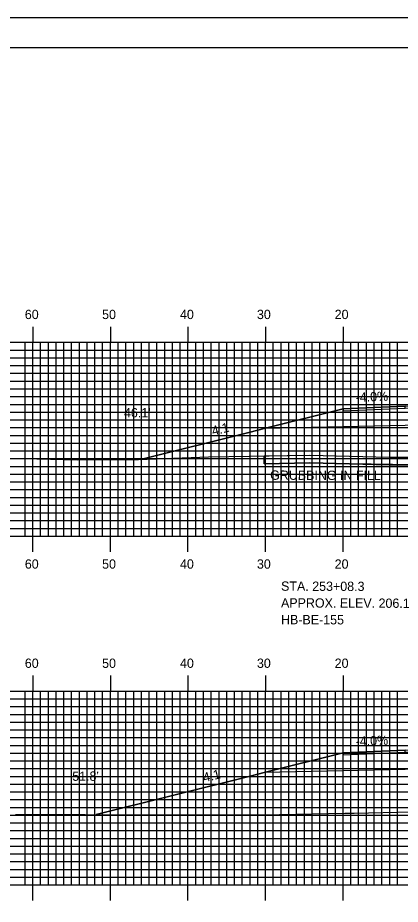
# Model space of a CAD drawing. Extents: x 1804290 to 1804634, y 442591 to 442811.
# Drawn here: x 1804394.2 to 1804443.5, y 442696.2 to 442810.5 of the extents above; entities that cross this region are included whole.
import ezdxf

# ---------------------------------------------------------------- set-up
doc = ezdxf.new("R2010")
doc.units = 0
for name, color, linetype in [('ANNOTATION', 7, 'Continuous'), ('BORDER', 7, 'Continuous'), ('BORING - REFUSAL', 7, 'Continuous'), ('D_Roadway_Centerline', 7, 'Continuous'), ('D_Roadway_Edge_Shoulder', 7, 'Continuous'), ('D_Roadway_SlopeLines', 7, 'Continuous'), ('D_Roadway_SubGrade', 7, 'Continuous'), ('D_Text_Standard', 7, 'Continuous'), ('GRUBBING IN FILL', 7, 'Continuous'), ('H_V ANNOTATION', 7, 'Continuous'), ('MAJOR', 7, 'Continuous'), ('MINOR', 7, 'Continuous'), ('PLOT BOUNDARY', 7, 'Continuous'), ('S_Roadway_Centerline', 7, 'Continuous')]:
    doc.layers.add(name, color=color, linetype=linetype)

msp = doc.modelspace()

# ---------------------------------------------------------------- linework, layer by layer
at = {"layer": 'BORDER'}
msp.add_lwpolyline([(1804306.57, 442596.67), (1804626.57, 442596.67), (1804626.57, 442806.67), (1804306.57, 442806.67)], close=True, dxfattribs=at)
at = {"layer": 'D_Roadway_Centerline'}
for points in [[(1804410.07, 442753.57), (1804424.17, 442757.1), (1804425.99, 442757.55), (1804436.17, 442760.1), (1804444.17, 442760.42), (1804456.17, 442760.71), (1804468.17, 442760.99), (1804476.17, 442760.67), (1804486.34, 442758.13), (1804501.85, 442754.25)], [(1804404.33, 442707.76), (1804424.17, 442712.72), (1804425.99, 442713.18), (1804436.17, 442715.72), (1804444.17, 442716.04), (1804456.17, 442716.33), (1804468.17, 442716.62), (1804476.17, 442716.3), (1804486.34, 442713.76), (1804508.15, 442708.3)]]:
    msp.add_lwpolyline(points, dxfattribs=at)
at = {"layer": 'D_Roadway_Edge_Shoulder'}
for points in [[(1804444.17, 442760.42), (1804436.17, 442760.1), (1804436.17, 442759.85), (1804444.17, 442760.17)], [(1804444.17, 442716.04), (1804436.17, 442715.72), (1804436.17, 442715.47), (1804444.17, 442715.79)]]:
    msp.add_lwpolyline(points, close=True, dxfattribs=at)
at = {"layer": 'D_Roadway_SlopeLines'}
for points in [[(1804436.17, 442760.1), (1804425.99, 442757.55), (1804424.17, 442757.1), (1804410.07, 442753.57)], [(1804436.17, 442715.72), (1804425.99, 442713.18), (1804424.17, 442712.72), (1804404.33, 442707.76)]]:
    msp.add_lwpolyline(points, dxfattribs=at)
at = {"layer": 'D_Roadway_SubGrade'}
for points in [[(1804444.17, 442757.92), (1804425.99, 442757.55), (1804436.17, 442760.1), (1804436.17, 442759.85), (1804444.17, 442760.17), (1804456.17, 442760.46), (1804468.17, 442760.74), (1804476.17, 442760.42), (1804476.17, 442760.67), (1804486.34, 442758.13), (1804468.17, 442758.49), (1804456.17, 442758.21)], [(1804444.17, 442713.54), (1804425.99, 442713.18), (1804436.17, 442715.72), (1804436.17, 442715.47), (1804444.17, 442715.79), (1804456.17, 442716.08), (1804468.17, 442716.37), (1804476.17, 442716.05), (1804476.17, 442716.3), (1804486.34, 442713.76), (1804468.17, 442714.12), (1804456.17, 442713.83)]]:
    msp.add_lwpolyline(points, close=True, dxfattribs=at)
at = {"layer": 'GRUBBING IN FILL'}
msp.add_line((1804425.99, 442754.01), (1804425.99, 442753.01), dxfattribs=at)
msp.add_line((1804425.99, 442754.01), (1804425.99, 442753.01), dxfattribs=at)
msp.add_lwpolyline([(1804425.99, 442753.01), (1804425.99, 442754.01), (1804431.89, 442754.11), (1804437, 442753.99), (1804442.11, 442753.87), (1804445.35, 442753.85), (1804452.2, 442753.85), (1804456.17, 442753.87), (1804456.17, 442752.87), (1804452.2, 442752.85), (1804448.59, 442752.84), (1804445.34, 442752.85), (1804436.99, 442752.99), (1804431.89, 442753.11)], close=True, dxfattribs=at)
msp.add_lwpolyline([(1804425.99, 442753.01), (1804425.99, 442754.01), (1804431.89, 442754.11), (1804437, 442753.99), (1804442.11, 442753.87), (1804445.35, 442753.85), (1804452.2, 442753.85), (1804456.17, 442753.87), (1804456.17, 442752.87), (1804452.2, 442752.85), (1804448.59, 442752.84), (1804445.34, 442752.85), (1804436.99, 442752.99), (1804431.89, 442753.11)], close=True, dxfattribs=at)
msp.add_lwpolyline([(1804425.99, 442753.01), (1804431.89, 442753.11), (1804442.1, 442752.87), (1804448.59, 442752.84), (1804455.82, 442752.87), (1804471.19, 442753.01), (1804478.09, 442753.25), (1804482.54, 442753.32), (1804486.34, 442753.29)], dxfattribs=at)
msp.add_lwpolyline([(1804425.99, 442753.01), (1804431.89, 442753.11), (1804442.1, 442752.87), (1804448.59, 442752.84), (1804455.82, 442752.87), (1804471.19, 442753.01), (1804478.09, 442753.25), (1804482.54, 442753.32), (1804486.34, 442753.29)], dxfattribs=at)
at = {"layer": 'MAJOR'}
for p, q in [((1804396.17, 442770.67), (1804396.17, 442768.67)), ((1804406.17, 442770.67), (1804406.17, 442768.67)), ((1804416.17, 442770.67), (1804416.17, 442768.67)), ((1804426.17, 442770.67), (1804426.17, 442768.67)), ((1804436.17, 442770.67), (1804436.17, 442768.67)), ((1804316.17, 442768.67), (1804596.17, 442768.67)), ((1804316.17, 442768.67), (1804596.17, 442768.67)), ((1804396.17, 442743.67), (1804396.17, 442768.67)), ((1804406.17, 442743.67), (1804406.17, 442768.67)), ((1804416.17, 442743.67), (1804416.17, 442768.67)), ((1804426.17, 442743.67), (1804426.17, 442768.67)), ((1804436.17, 442743.67), (1804436.17, 442768.67)), ((1804316.17, 442763.67), (1804596.17, 442763.67)), ((1804316.17, 442758.67), (1804596.17, 442758.67)), ((1804316.17, 442753.67), (1804596.17, 442753.67)), ((1804316.17, 442748.67), (1804596.17, 442748.67)), ((1804316.17, 442743.67), (1804596.17, 442743.67)), ((1804316.17, 442743.67), (1804596.17, 442743.67)), ((1804396.17, 442741.66), (1804396.17, 442743.67)), ((1804406.17, 442741.66), (1804406.17, 442743.67)), ((1804416.17, 442741.66), (1804416.17, 442743.67)), ((1804426.17, 442741.66), (1804426.17, 442743.67)), ((1804436.17, 442741.66), (1804436.17, 442743.67)), ((1804396.17, 442725.67), (1804396.17, 442723.67)), ((1804406.17, 442725.67), (1804406.17, 442723.67)), ((1804416.17, 442725.67), (1804416.17, 442723.67)), ((1804426.17, 442725.67), (1804426.17, 442723.67)), ((1804436.17, 442725.67), (1804436.17, 442723.67)), ((1804316.17, 442723.67), (1804596.17, 442723.67)), ((1804316.17, 442723.67), (1804596.17, 442723.67)), ((1804396.17, 442698.67), (1804396.17, 442723.67)), ((1804406.17, 442698.67), (1804406.17, 442723.67)), ((1804416.17, 442698.67), (1804416.17, 442723.67)), ((1804426.17, 442698.67), (1804426.17, 442723.67)), ((1804436.17, 442698.67), (1804436.17, 442723.67)), ((1804316.17, 442718.67), (1804596.17, 442718.67)), ((1804316.17, 442713.67), (1804596.17, 442713.67)), ((1804316.17, 442708.67), (1804596.17, 442708.67)), ((1804316.17, 442703.67), (1804596.17, 442703.67)), ((1804316.17, 442698.67), (1804596.17, 442698.67)), ((1804316.17, 442698.67), (1804596.17, 442698.67)), ((1804396.17, 442696.66), (1804396.17, 442698.67)), ((1804406.17, 442696.66), (1804406.17, 442698.67)), ((1804416.17, 442696.66), (1804416.17, 442698.67)), ((1804426.17, 442696.66), (1804426.17, 442698.67)), ((1804436.17, 442696.66), (1804436.17, 442698.67))]:
    msp.add_line(p, q, dxfattribs=at)
at = {"layer": 'MINOR'}
for p, q in [((1804316.17, 442767.67), (1804596.17, 442767.67)), ((1804395.17, 442743.67), (1804395.17, 442768.67)), ((1804397.17, 442743.67), (1804397.17, 442768.67)), ((1804398.17, 442743.67), (1804398.17, 442768.67)), ((1804399.17, 442743.67), (1804399.17, 442768.67)), ((1804400.17, 442743.67), (1804400.17, 442768.67)), ((1804401.17, 442743.67), (1804401.17, 442768.67)), ((1804402.17, 442743.67), (1804402.17, 442768.67)), ((1804403.17, 442743.67), (1804403.17, 442768.67)), ((1804404.17, 442743.67), (1804404.17, 442768.67)), ((1804405.17, 442743.67), (1804405.17, 442768.67)), ((1804407.17, 442743.67), (1804407.17, 442768.67)), ((1804408.17, 442743.67), (1804408.17, 442768.67)), ((1804409.17, 442743.67), (1804409.17, 442768.67)), ((1804410.17, 442743.67), (1804410.17, 442768.67)), ((1804411.17, 442743.67), (1804411.17, 442768.67)), ((1804412.17, 442743.67), (1804412.17, 442768.67)), ((1804413.17, 442743.67), (1804413.17, 442768.67)), ((1804414.17, 442743.67), (1804414.17, 442768.67)), ((1804415.17, 442743.67), (1804415.17, 442768.67)), ((1804417.17, 442743.67), (1804417.17, 442768.67)), ((1804418.17, 442743.67), (1804418.17, 442768.67)), ((1804419.17, 442743.67), (1804419.17, 442768.67)), ((1804420.17, 442743.67), (1804420.17, 442768.67)), ((1804421.17, 442743.67), (1804421.17, 442768.67)), ((1804422.17, 442743.67), (1804422.17, 442768.67)), ((1804423.17, 442743.67), (1804423.17, 442768.67)), ((1804424.17, 442743.67), (1804424.17, 442768.67)), ((1804425.17, 442743.67), (1804425.17, 442768.67)), ((1804427.17, 442743.67), (1804427.17, 442768.67)), ((1804428.17, 442743.67), (1804428.17, 442768.67)), ((1804429.17, 442743.67), (1804429.17, 442768.67)), ((1804430.17, 442743.67), (1804430.17, 442768.67)), ((1804431.17, 442743.67), (1804431.17, 442768.67)), ((1804432.17, 442743.67), (1804432.17, 442768.67)), ((1804433.17, 442743.67), (1804433.17, 442768.67)), ((1804434.17, 442743.67), (1804434.17, 442768.67)), ((1804435.17, 442743.67), (1804435.17, 442768.67)), ((1804437.17, 442743.67), (1804437.17, 442768.67)), ((1804438.17, 442743.67), (1804438.17, 442768.67)), ((1804439.17, 442743.67), (1804439.17, 442768.67)), ((1804440.17, 442743.67), (1804440.17, 442768.67)), ((1804441.17, 442743.67), (1804441.17, 442768.67)), ((1804442.17, 442743.67), (1804442.17, 442768.67)), ((1804443.17, 442743.67), (1804443.17, 442768.67)), ((1804316.17, 442766.67), (1804596.17, 442766.67)), ((1804316.17, 442765.67), (1804596.17, 442765.67)), ((1804316.17, 442764.67), (1804596.17, 442764.67)), ((1804316.17, 442762.67), (1804596.17, 442762.67)), ((1804316.17, 442761.67), (1804596.17, 442761.67)), ((1804316.17, 442760.67), (1804596.17, 442760.67)), ((1804316.17, 442759.67), (1804596.17, 442759.67)), ((1804316.17, 442757.67), (1804596.17, 442757.67)), ((1804316.17, 442756.67), (1804596.17, 442756.67)), ((1804316.17, 442755.67), (1804596.17, 442755.67)), ((1804316.17, 442754.67), (1804596.17, 442754.67)), ((1804316.17, 442752.67), (1804596.17, 442752.67)), ((1804316.17, 442751.67), (1804596.17, 442751.67)), ((1804316.17, 442750.67), (1804596.17, 442750.67)), ((1804316.17, 442749.67), (1804596.17, 442749.67)), ((1804316.17, 442747.67), (1804596.17, 442747.67)), ((1804316.17, 442746.67), (1804596.17, 442746.67)), ((1804316.17, 442745.67), (1804596.17, 442745.67)), ((1804316.17, 442744.67), (1804596.17, 442744.67)), ((1804395.17, 442698.67), (1804395.17, 442723.67)), ((1804397.17, 442698.67), (1804397.17, 442723.67)), ((1804398.17, 442698.67), (1804398.17, 442723.67)), ((1804399.17, 442698.67), (1804399.17, 442723.67)), ((1804400.17, 442698.67), (1804400.17, 442723.67)), ((1804401.17, 442698.67), (1804401.17, 442723.67)), ((1804402.17, 442698.67), (1804402.17, 442723.67)), ((1804403.17, 442698.67), (1804403.17, 442723.67)), ((1804404.17, 442698.67), (1804404.17, 442723.67)), ((1804405.17, 442698.67), (1804405.17, 442723.67)), ((1804407.17, 442698.67), (1804407.17, 442723.67)), ((1804408.17, 442698.67), (1804408.17, 442723.67)), ((1804409.17, 442698.67), (1804409.17, 442723.67)), ((1804410.17, 442698.67), (1804410.17, 442723.67)), ((1804411.17, 442698.67), (1804411.17, 442723.67)), ((1804412.17, 442698.67), (1804412.17, 442723.67)), ((1804413.17, 442698.67), (1804413.17, 442723.67)), ((1804414.17, 442698.67), (1804414.17, 442723.67)), ((1804415.17, 442698.67), (1804415.17, 442723.67)), ((1804417.17, 442698.67), (1804417.17, 442723.67)), ((1804418.17, 442698.67), (1804418.17, 442723.67)), ((1804419.17, 442698.67), (1804419.17, 442723.67)), ((1804420.17, 442698.67), (1804420.17, 442723.67)), ((1804421.17, 442698.67), (1804421.17, 442723.67)), ((1804422.17, 442698.67), (1804422.17, 442723.67)), ((1804423.17, 442698.67), (1804423.17, 442723.67)), ((1804424.17, 442698.67), (1804424.17, 442723.67)), ((1804425.17, 442698.67), (1804425.17, 442723.67)), ((1804427.17, 442698.67), (1804427.17, 442723.67)), ((1804428.17, 442698.67), (1804428.17, 442723.67)), ((1804429.17, 442698.67), (1804429.17, 442723.67)), ((1804430.17, 442698.67), (1804430.17, 442723.67)), ((1804431.17, 442698.67), (1804431.17, 442723.67)), ((1804432.17, 442698.67), (1804432.17, 442723.67)), ((1804433.17, 442698.67), (1804433.17, 442723.67)), ((1804434.17, 442698.67), (1804434.17, 442723.67)), ((1804435.17, 442698.67), (1804435.17, 442723.67)), ((1804437.17, 442698.67), (1804437.17, 442723.67)), ((1804438.17, 442698.67), (1804438.17, 442723.67)), ((1804439.17, 442698.67), (1804439.17, 442723.67)), ((1804440.17, 442698.67), (1804440.17, 442723.67)), ((1804441.17, 442698.67), (1804441.17, 442723.67)), ((1804442.17, 442698.67), (1804442.17, 442723.67)), ((1804443.17, 442698.67), (1804443.17, 442723.67)), ((1804316.17, 442722.67), (1804596.17, 442722.67)), ((1804316.17, 442721.67), (1804596.17, 442721.67)), ((1804316.17, 442720.67), (1804596.17, 442720.67)), ((1804316.17, 442719.67), (1804596.17, 442719.67)), ((1804316.17, 442717.67), (1804596.17, 442717.67)), ((1804316.17, 442716.67), (1804596.17, 442716.67)), ((1804316.17, 442715.67), (1804596.17, 442715.67)), ((1804316.17, 442714.67), (1804596.17, 442714.67)), ((1804316.17, 442712.67), (1804596.17, 442712.67)), ((1804316.17, 442711.67), (1804596.17, 442711.67)), ((1804316.17, 442710.67), (1804596.17, 442710.67)), ((1804316.17, 442709.67), (1804596.17, 442709.67)), ((1804316.17, 442707.67), (1804596.17, 442707.67)), ((1804316.17, 442706.67), (1804596.17, 442706.67)), ((1804316.17, 442705.67), (1804596.17, 442705.67)), ((1804316.17, 442704.67), (1804596.17, 442704.67)), ((1804316.17, 442702.67), (1804596.17, 442702.67)), ((1804316.17, 442701.67), (1804596.17, 442701.67)), ((1804316.17, 442700.67), (1804596.17, 442700.67)), ((1804316.17, 442699.67), (1804596.17, 442699.67))]:
    msp.add_line(p, q, dxfattribs=at)
at = {"layer": 'PLOT BOUNDARY'}
msp.add_lwpolyline([(1804290.38, 442590.55), (1804630.38, 442590.55), (1804630.38, 442810.55), (1804290.38, 442810.55)], close=True, dxfattribs=at)
at = {"layer": 'S_Roadway_Centerline'}
for points in [[(1804390.07, 442753.77), (1804394.91, 442753.68), (1804401.92, 442753.5), (1804409.8, 442753.56), (1804418.83, 442753.9), (1804431.89, 442754.11), (1804442.11, 442753.87), (1804448.59, 442753.84), (1804455.81, 442753.87), (1804471.17, 442754.01), (1804478.07, 442754.25), (1804482.53, 442754.32), (1804486.78, 442754.29), (1804494.66, 442754.11), (1804503.03, 442754.28), (1804507.3, 442754.28), (1804511.52, 442754.56), (1804526.57, 442754.69)], [(1804393.95, 442707.75), (1804402.91, 442707.77), (1804411.61, 442707.71), (1804416.48, 442707.71), (1804425.87, 442707.73), (1804436.37, 442707.91), (1804437.59, 442707.92), (1804452.47, 442708.28), (1804459.91, 442708.44), (1804461.13, 442708.46), (1804484.96, 442708.31), (1804495.8, 442708.13), (1804506.33, 442708.31), (1804507.56, 442708.31), (1804518.78, 442708.2)]]:
    msp.add_lwpolyline(points, dxfattribs=at)

# ---------------------------------------------------------------- texts
at = {"layer": 'ANNOTATION'}
for s, rotation, p in [('-4.0%', 2.2906, (1804437.8, 442760.97)), ('4:1', 14.0362, (1804419.4, 442756.63)), ('-4.0%', 2.2906, (1804437.8, 442716.59)), ('4:1', 14.0362, (1804418.28, 442711.9))]:
    msp.add_text(s, height=1.2, rotation=rotation, dxfattribs=at).set_placement(p)
at = {"layer": 'BORING - REFUSAL'}
for s, p in [('STA. 253+08.3', (1804428.17, 442736.62)), ('APPROX. ELEV. 206.1', (1804428.16, 442734.46)), ('HB-BE-155', (1804428.16, 442732.3))]:
    msp.add_text(s, height=1.2, rotation=359.8142, dxfattribs=at).set_placement(p)
at = {"layer": 'D_Text_Standard'}
for s, p in [("46.1'", (1804407.92, 442758.99)), ("51.8'", (1804401.25, 442712.1))]:
    msp.add_text(s, height=1.2, dxfattribs=at).set_placement(p)
at = {"layer": 'GRUBBING IN FILL'}
msp.add_text('GRUBBING IN FILL', height=1.2, rotation=359.8053, dxfattribs=at).set_placement((1804426.76, 442750.94))
at = {"layer": 'H_V ANNOTATION'}
for s, p in [('60', (1804395.14, 442771.67)), ('50', (1804405.1, 442771.67)), ('40', (1804415.14, 442771.67)), ('30', (1804425.06, 442771.67)), ('20', (1804435.08, 442771.67)), ('60', (1804395.14, 442739.47)), ('50', (1804405.1, 442739.47)), ('40', (1804415.14, 442739.47)), ('30', (1804425.06, 442739.47)), ('20', (1804435.08, 442739.47)), ('60', (1804395.14, 442726.67)), ('50', (1804405.1, 442726.67)), ('40', (1804415.14, 442726.67)), ('30', (1804425.06, 442726.67)), ('20', (1804435.08, 442726.67))]:
    msp.add_text(s, height=1.2, dxfattribs=at).set_placement(p)

doc.saveas('drawing.dxf')
